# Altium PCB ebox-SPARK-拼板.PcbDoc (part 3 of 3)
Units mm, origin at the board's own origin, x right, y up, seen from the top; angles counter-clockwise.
Board outline 102 x 90 mm, 2 copper layers (Top Layer, Bottom Layer); 141 components, 68 nets, 621 pads, 146 vias.
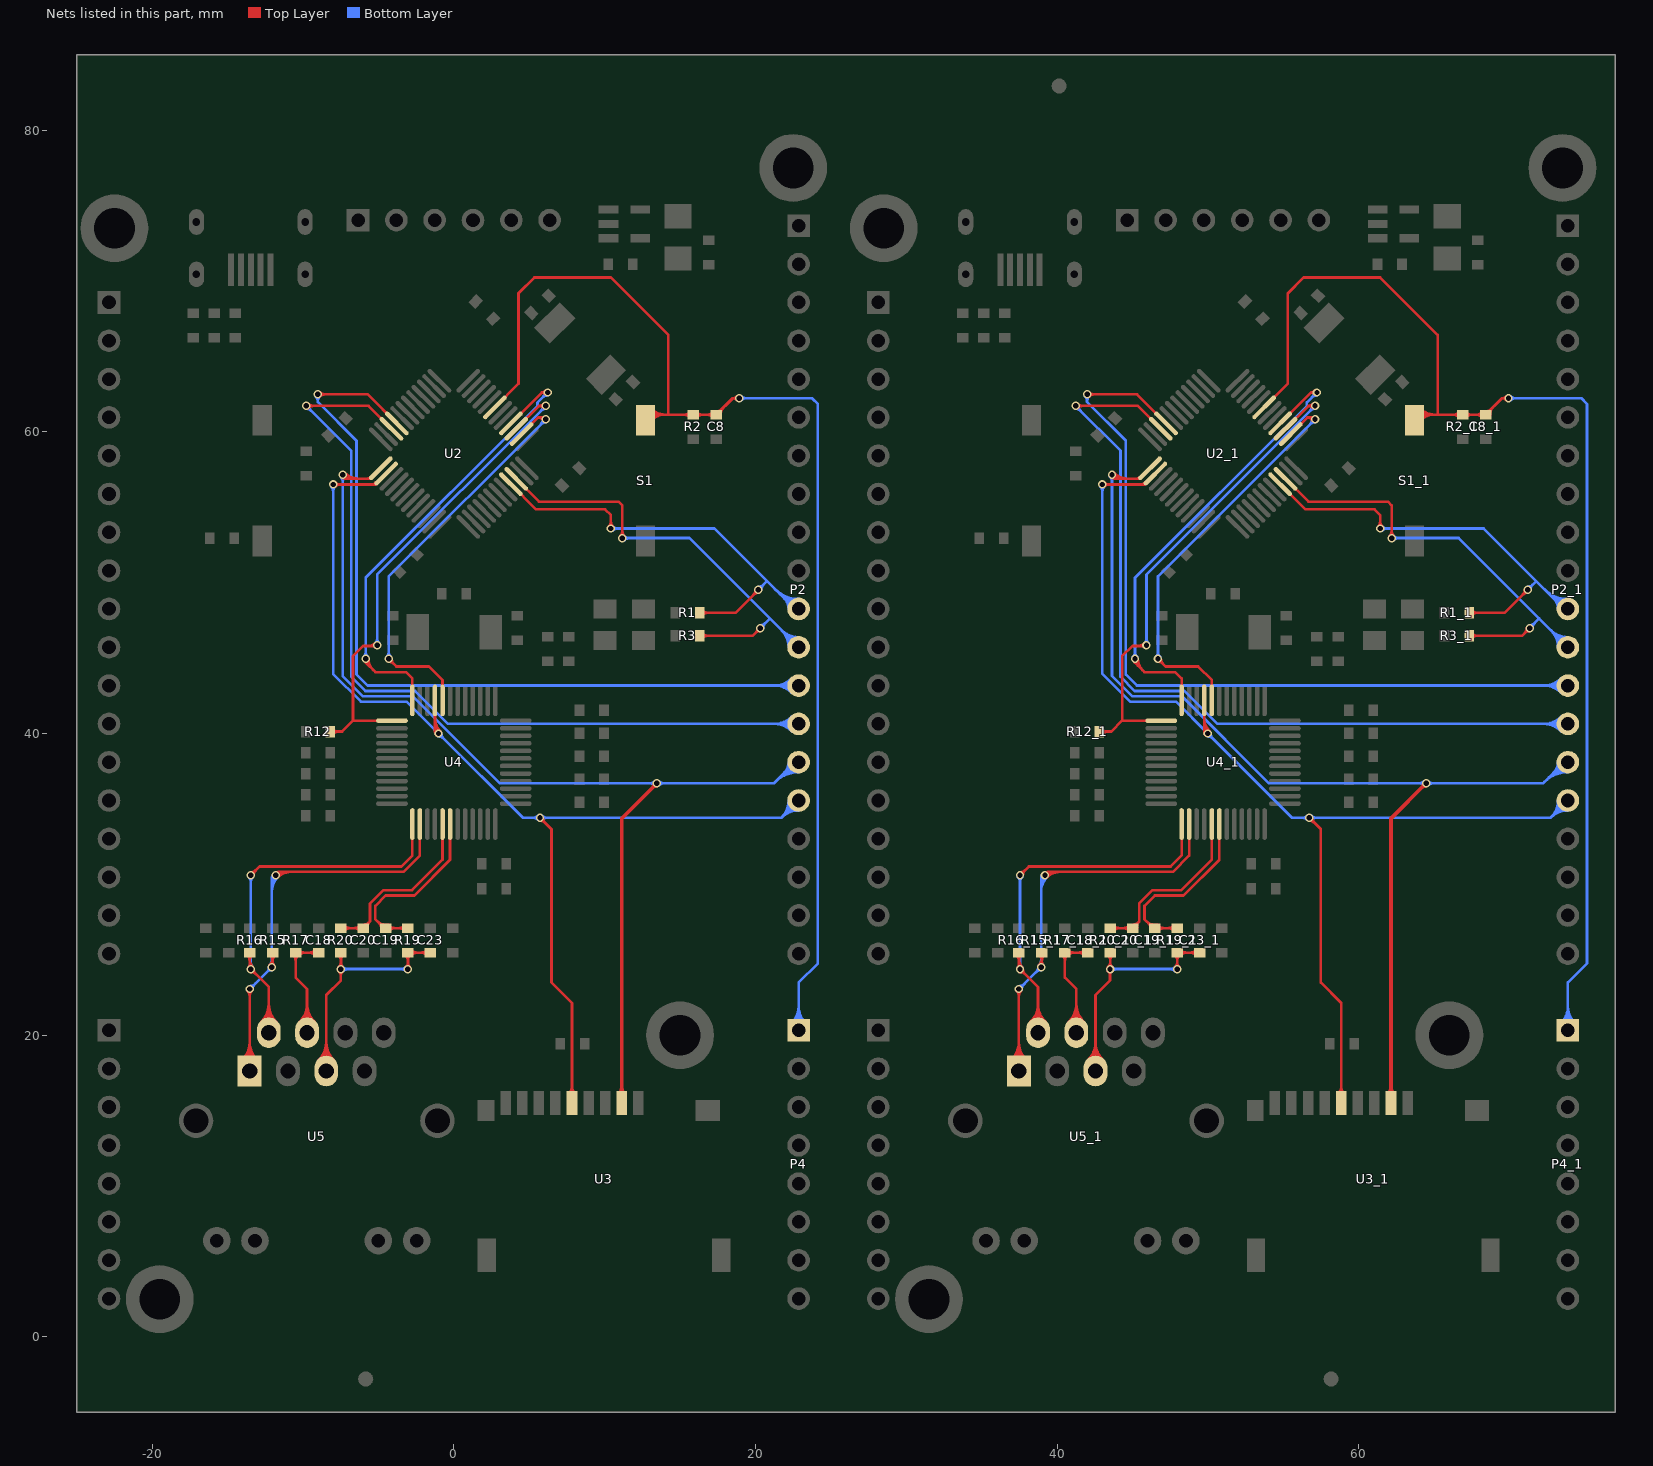
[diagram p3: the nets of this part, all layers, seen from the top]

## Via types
v1: diameter 0.559, hole 0.356, Top Layer to Bottom Layer, tented both sides, 140 vias
v2: diameter 1, hole 1, Top Layer to Bottom Layer, tented both sides, 4 vias
v3: diameter 1.27, hole 0.711, Top Layer to Bottom Layer, tented both sides, 2 vias

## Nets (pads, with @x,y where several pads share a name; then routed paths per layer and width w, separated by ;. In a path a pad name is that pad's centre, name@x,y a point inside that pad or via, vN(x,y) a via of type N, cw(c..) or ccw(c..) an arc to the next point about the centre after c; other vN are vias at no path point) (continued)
PB8: P2.11 P2_1.11 R1.1 R1_1.1 U2.45 U2_1.45 | length 76.4
  Top Layer w0.178: U2.45@3.783,56.532 5.451,54.864 10.033,54.864 10.414,54.483 v1(10.414,53.594) ; v1@10.279,53.729 ccw(c9.954,54.054) 10.414,54.054 ccw(c10.874,54.054) v1@10.549,53.729 ; R1.1@16.307,48.006 18.669,48.006 v1(20.193,49.53) ; R1.1@16.468,47.844 cw(c16.859,47.454) 16.859,48.006 cw(c16.859,48.558) R1.1@16.468,48.168 ; v1@20.002,49.53 cw(c19.543,49.53) 19.868,49.205 cw(c20.193,48.88) v1@20.193,49.34 ; U2_1.45@54.783,56.532 56.451,54.864 61.033,54.864 61.414,54.483 v1(61.414,53.594) ; v1@61.279,53.729 ccw(c60.954,54.054) 61.414,54.054 ccw(c61.874,54.054) v1@61.549,53.729 ; R1_1.1@67.307,48.006 69.669,48.006 v1(71.193,49.53) ; R1_1.1@67.468,47.844 cw(c67.859,47.454) 67.859,48.006 cw(c67.859,48.558) R1_1.1@67.468,48.168 ; v1@71.002,49.53 cw(c70.543,49.53) 70.868,49.205 cw(c71.193,48.88) v1@71.193,49.34
  Bottom Layer w0.178: v1(10.414,53.594) 17.272,53.594 22.606,48.26 P2.11@22.86,48.26 ; v1@10.549,53.459 cw(c10.874,53.134) 10.874,53.594 cw(c10.874,54.054) v1@10.549,53.729 ; v1(20.193,49.53) 20.735,50.072 ; v1@20.193,49.721 ccw(c20.193,50.18) 20.518,49.855 ccw(c20.843,49.53) v1@20.383,49.53 ; 21.298,49.568 ccw(c22.86,51.13) P2.11@22.86,48.921 ; 21.601,49.265 ccw(c22.86,50.523) P2.11@22.86,48.743 ; 21.905,48.961 ccw(c22.86,49.916) P2.11@22.86,48.565 ; 21.911,48.955 cw(c21.216,48.26) P2.11@22.199,48.26 ; 22.208,48.658 ccw(c22.86,49.309) P2.11@22.86,48.388 ; 22.215,48.651 cw(c21.823,48.26) P2.11@22.377,48.26 ; v1(61.414,53.594) 68.272,53.594 73.606,48.26 P2_1.11@73.86,48.26 ; v1@61.549,53.459 cw(c61.874,53.134) 61.874,53.594 cw(c61.874,54.054) v1@61.549,53.729 ; v1(71.193,49.53) 71.735,50.072 ; v1@71.193,49.721 ccw(c71.193,50.18) 71.518,49.855 ccw(c71.843,49.53) v1@71.383,49.53 ; 72.298,49.568 ccw(c73.86,51.13) P2_1.11@73.86,48.921 ; 72.601,49.265 ccw(c73.86,50.523) P2_1.11@73.86,48.743 ; 72.905,48.961 ccw(c73.86,49.916) P2_1.11@73.86,48.565 ; 72.911,48.955 cw(c72.216,48.26) P2_1.11@73.199,48.26 ; 73.208,48.658 ccw(c73.86,49.309) P2_1.11@73.86,48.388 ; 73.215,48.651 cw(c72.823,48.26) P2_1.11@73.377,48.26
PB9: P2.12 P2_1.12 R3.1 R3_1.1 U2.46 U2_1.46 | length 75.9
  Top Layer w0.178: U2.46@4.137,56.885 5.65,55.372 10.922,55.372 11.176,55.118 v1(11.176,52.959) ; v1@11.041,53.094 ccw(c10.716,53.419) 11.176,53.419 ccw(c11.636,53.419) v1@11.311,53.094 ; R3.1@16.307,46.482 19.812,46.482 v1(20.32,46.99) v1@20.193,46.99 ; R3.1@16.468,46.32 cw(c16.859,45.93) 16.859,46.482 cw(c16.859,47.034) R3.1@16.468,46.644 ; v1@20.13,46.99 cw(c19.67,46.99) 19.995,46.665 cw(c20.32,46.34) v1@20.32,46.799 ; U2_1.46@55.137,56.885 56.65,55.372 61.922,55.372 62.176,55.118 v1(62.176,52.959) ; v1@62.041,53.094 ccw(c61.716,53.419) 62.176,53.419 ccw(c62.636,53.419) v1@62.311,53.094 ; R3_1.1@67.307,46.482 70.812,46.482 v1(71.32,46.99) v1@71.193,46.99 ; R3_1.1@67.468,46.32 cw(c67.859,45.93) 67.859,46.482 cw(c67.859,47.034) R3_1.1@67.468,46.644 ; v1@71.129,46.99 cw(c70.67,46.99) 70.995,46.665 cw(c71.32,46.34) v1@71.32,46.799
  Bottom Layer w0.178: v1(11.176,52.959) 15.621,52.959 20.955,47.625 ; v1@11.311,52.824 cw(c11.636,52.499) 11.636,52.959 cw(c11.636,53.419) v1@11.311,53.094 ; v1(20.32,46.99) 20.955,47.625 ; v1@20.32,47.18 ccw(c20.32,47.64) 20.645,47.315 ccw(c20.97,46.99) v1@20.51,46.99 ; P2.12@22.199,45.72 ccw(c20.603,45.72) 21.731,46.849 ccw(c22.86,47.977) P2.12@22.86,46.381 ; P2.12@22.377,45.72 ccw(c21.21,45.72) 22.035,46.545 ccw(c22.86,47.37) P2.12@22.86,46.203 ; P2.12@22.86,45.72 20.955,47.625 ; v1(62.176,52.959) 66.621,52.959 71.955,47.625 ; v1@62.311,52.824 cw(c62.636,52.499) 62.636,52.959 cw(c62.636,53.419) v1@62.311,53.094 ; v1(71.32,46.99) 71.955,47.625 ; v1@71.32,47.18 ccw(c71.32,47.64) 71.645,47.315 ccw(c71.97,46.99) v1@71.51,46.99 ; P2_1.12@73.199,45.72 ccw(c71.603,45.72) 72.731,46.849 ccw(c73.86,47.977) P2_1.12@73.86,46.381 ; P2_1.12@73.377,45.72 ccw(c72.21,45.72) 73.035,46.545 ccw(c73.86,47.37) P2_1.12@73.86,46.203 ; P2_1.12@73.86,45.72 71.955,47.625
PB10: P2.13 P2_1.13 U2.21 U2_1.21 | length 122.1
  Top Layer w0.178: v1(-9.017,62.484) -5.705,62.484 U2.21@-3.783,60.562 ; v1@-8.882,62.349 cw(c-8.557,62.024) -8.557,62.484 cw(c-8.557,62.944) v1@-8.882,62.619 ; v1(41.983,62.484) 45.295,62.484 U2_1.21@47.217,60.562 ; v1@42.118,62.349 cw(c42.443,62.024) 42.443,62.484 cw(c42.443,62.944) v1@42.118,62.619
  Bottom Layer w0.178: v1@-9.152,62.349 cw(c-9.477,62.024) -9.017,62.024 cw(c-8.557,62.024) v1@-8.882,62.349 ; v1(-9.017,62.484) -9.017,61.976 -6.452,59.411 -6.452,43.917 -5.715,43.18 19.558,43.18 P2.13@22.86,43.18 ; P2.13@22.393,42.713 ccw(c21.264,41.584) 21.264,43.18 ccw(c21.264,44.776) P2.13@22.393,43.647 ; P2.13@22.518,42.838 ccw(c21.693,42.013) 21.693,43.18 ccw(c21.693,44.347) P2.13@22.518,43.522 ; v1@41.848,62.349 cw(c41.523,62.024) 41.983,62.024 cw(c42.443,62.024) v1@42.118,62.349 ; v1(41.983,62.484) 41.983,61.976 44.548,59.411 44.548,43.917 45.285,43.18 70.558,43.18 P2_1.13@73.86,43.18 ; P2_1.13@73.393,42.713 ccw(c72.264,41.584) 72.264,43.18 ccw(c72.264,44.776) P2_1.13@73.393,43.647 ; P2_1.13@73.518,42.838 ccw(c72.693,42.013) 72.693,43.18 ccw(c72.693,44.347) P2_1.13@73.518,43.522
PB11: P2.14 P2_1.14 U2.22 U2_1.22 | length 124.4
  Top Layer w0.178: v1(-9.779,61.722) -5.65,61.722 U2.22@-4.137,60.209 ; v1@-9.644,61.587 cw(c-9.319,61.262) -9.319,61.722 cw(c-9.319,62.182) v1@-9.644,61.857 ; v1(41.221,61.722) 45.35,61.722 U2_1.22@46.863,60.209 ; v1@41.356,61.587 cw(c41.681,61.262) 41.681,61.722 cw(c41.681,62.182) v1@41.356,61.857
  Bottom Layer w0.178: v1@-9.779,61.531 cw(c-9.779,61.072) -9.454,61.397 cw(c-9.129,61.722) v1@-9.589,61.722 ; v1(-9.779,61.722) -6.807,58.75 -6.807,43.769 -5.862,42.824 -2.56,42.824 -0.376,40.64 P2.14@22.86,40.64 ; P2.14@22.393,40.173 ccw(c21.264,39.044) 21.264,40.64 ccw(c21.264,42.236) P2.14@22.393,41.107 ; P2.14@22.518,40.298 ccw(c21.693,39.473) 21.693,40.64 ccw(c21.693,41.807) P2.14@22.518,40.982 ; v1@41.221,61.531 cw(c41.221,61.072) 41.546,61.397 cw(c41.871,61.722) v1@41.411,61.722 ; v1(41.221,61.722) 44.193,58.75 44.193,43.769 45.138,42.824 48.44,42.824 50.624,40.64 P2_1.14@73.86,40.64 ; P2_1.14@73.393,40.173 ccw(c72.264,39.044) 72.264,40.64 ccw(c72.264,42.236) P2_1.14@73.393,41.107 ; P2_1.14@73.518,40.298 ccw(c72.693,39.473) 72.693,40.64 ccw(c72.693,41.807) P2_1.14@73.518,40.982
PB12: P2.15 P2_1.15 U2.25 U2_1.25 U3.2 U3_1.2 | length 168.5
  Top Layer w0.178: v1@-7.483,57.033 ccw(c-7.151,57.365) -7.151,56.896 ; v1(-7.366,57.15) -7.112,56.896 -5.54,56.896 U2.25@-4.844,57.592 ; v1@-7.357,57.159 ccw(c-6.722,57.794) -6.722,56.896 ; v1@-7.231,57.285 ccw(c-6.293,58.223) -6.293,56.896 ; -5.772,56.896 ccw(c-5.772,57.248) U2.25@-5.523,56.999 ; v1@43.517,57.033 ccw(c43.849,57.365) 43.849,56.896 ; v1(43.634,57.15) 43.888,56.896 45.46,56.896 U2_1.25@46.156,57.592 ; v1@43.643,57.159 ccw(c44.278,57.794) 44.278,56.896 ; v1@43.769,57.285 ccw(c44.707,58.223) 44.707,56.896 ; 45.228,56.896 ccw(c45.228,57.248) U2_1.25@45.477,56.999
  Top Layer w0.254: U3.2@10.975,16.122 ccw(c10.594,16.503) 11.133,16.503 ccw(c11.671,16.503) U3.2@11.29,16.122 ; U3.2@11.133,15.515 11.133,34.374 v1(13.462,36.703) ; v1@13.31,36.703 cw(c12.942,36.703) 13.202,36.443 cw(c13.462,36.183) v1@13.462,36.551 ; U3_1.2@61.975,16.122 ccw(c61.594,16.503) 62.133,16.503 ccw(c62.671,16.503) U3_1.2@62.29,16.122 ; U3_1.2@62.133,15.515 62.133,34.374 v1(64.462,36.703) ; v1@64.31,36.703 cw(c63.942,36.703) 64.202,36.443 cw(c64.462,36.183) v1@64.462,36.551
  Bottom Layer w0.178: v1@-7.501,57.015 cw(c-7.826,56.69) -7.366,56.69 cw(c-6.906,56.69) v1@-7.231,57.015 ; v1(-7.366,57.15) -7.366,43.825 -6.01,42.469 -2.708,42.469 3.058,36.703 v1(13.462,36.703) 21.209,36.703 22.606,38.1 P2.15@22.86,38.1 ; v1@13.327,36.568 ccw(c13.002,36.243) 13.002,36.703 ccw(c13.002,37.163) v1@13.327,36.838 ; v1@13.597,36.568 cw(c13.922,36.243) 13.922,36.703 cw(c13.922,37.163) v1@13.597,36.838 ; 21.298,36.792 cw(c22.86,35.23) P2.15@22.86,37.439 ; 21.601,37.095 cw(c22.86,35.837) P2.15@22.86,37.617 ; 21.905,37.399 cw(c22.86,36.444) P2.15@22.86,37.795 ; 21.911,37.405 ccw(c21.216,38.1) P2.15@22.199,38.1 ; 22.208,37.702 cw(c22.86,37.051) P2.15@22.86,37.972 ; 22.215,37.709 ccw(c21.823,38.1) P2.15@22.377,38.1 ; v1@43.499,57.015 cw(c43.174,56.69) 43.634,56.69 cw(c44.094,56.69) v1@43.769,57.015 ; v1(43.634,57.15) 43.634,43.825 44.99,42.469 48.292,42.469 54.058,36.703 v1(64.462,36.703) 72.209,36.703 73.606,38.1 P2_1.15@73.86,38.1 ; v1@64.327,36.568 ccw(c64.002,36.243) 64.002,36.703 ccw(c64.002,37.163) v1@64.327,36.838 ; v1@64.597,36.568 cw(c64.922,36.243) 64.922,36.703 cw(c64.922,37.163) v1@64.597,36.838 ; 72.298,36.792 cw(c73.86,35.23) P2_1.15@73.86,37.439 ; 72.601,37.095 cw(c73.86,35.837) P2_1.15@73.86,37.617 ; 72.905,37.399 cw(c73.86,36.444) P2_1.15@73.86,37.795 ; 72.911,37.405 ccw(c72.216,38.1) P2_1.15@73.199,38.1 ; 73.208,37.702 cw(c73.86,37.051) P2_1.15@73.86,37.972 ; 73.215,37.709 ccw(c72.823,38.1) P2_1.15@73.377,38.1
PB13: P2.16 P2_1.16 U2.26 U2_1.26 U3.5 U3_1.5 U4.33 U4_1.33 | length 172.8
  Top Layer w0.178: v1(-8.001,56.515) -5.214,56.515 U2.26@-4.49,57.239 ; v1@-7.866,56.38 cw(c-7.541,56.055) -7.541,56.515 cw(c-7.541,56.975) v1@-7.866,56.65 ; -5.485,56.515 ccw(c-5.485,56.961) U2.26@-5.17,56.646 ; -1.25,40.171 ccw(c-0.85,40.171) v1@-1.133,39.888 ; -1.25,40.601 ccw(c-0.42,40.601) v1@-1.007,40.014 ; -1.25,41.03 ccw(c0.009,41.03) v1@-0.881,40.14 ; U4.33@-1.25,42.2 -1.25,40.239 v1(-1.016,40.005) ; v1@5.715,34.227 cw(c5.715,33.767) 6.04,34.092 cw(c6.365,34.417) v1@5.905,34.417 ; v1(5.715,34.417) 6.477,33.655 6.477,23.495 7.833,22.139 U3.5@7.833,15.515 ; U3.5@7.648,16.149 ccw(c7.202,16.595) 7.833,16.595 ccw(c8.463,16.595) U3.5@8.017,16.149 ; v1(42.999,56.515) 45.786,56.515 U2_1.26@46.51,57.239 ; v1@43.134,56.38 cw(c43.459,56.055) 43.459,56.515 cw(c43.459,56.975) v1@43.134,56.65 ; 45.515,56.515 ccw(c45.515,56.961) U2_1.26@45.83,56.646 ; 49.75,40.171 ccw(c50.15,40.171) v1@49.867,39.888 ; 49.75,40.601 ccw(c50.58,40.601) v1@49.993,40.014 ; 49.75,41.03 ccw(c51.009,41.03) v1@50.119,40.14 ; U4_1.33@49.75,42.2 49.75,40.239 v1(49.984,40.005) ; v1@56.715,34.227 cw(c56.715,33.767) 57.04,34.092 cw(c57.365,34.417) v1@56.905,34.417 ; v1(56.715,34.417) 57.477,33.655 57.477,23.495 58.833,22.139 U3_1.5@58.833,15.515 ; U3_1.5@58.648,16.149 ccw(c58.202,16.595) 58.833,16.595 ccw(c59.463,16.595) U3_1.5@59.017,16.149
  Bottom Layer w0.178: v1@-8.136,56.38 cw(c-8.461,56.055) -8.001,56.055 cw(c-7.541,56.055) v1@-7.866,56.38 ; v1(-8.001,56.515) -8.001,43.957 -6.157,42.113 -3.124,42.113 v1(-1.016,40.005) 4.572,34.417 21.717,34.417 P2.16@22.86,35.56 ; v1@-1.206,40.005 ccw(c-1.666,40.005) -1.341,40.33 ccw(c-1.016,40.655) v1@-1.016,40.195 ; v1@-1.016,39.814 cw(c-1.016,39.355) -0.691,39.68 cw(c-0.366,40.005) v1@-0.826,40.005 ; v1@5.58,34.282 ccw(c5.255,33.957) 5.255,34.417 ccw(c5.255,34.877) v1@5.58,34.552 ; v1@5.85,34.282 cw(c6.175,33.957) 6.175,34.417 cw(c6.175,34.877) v1@5.85,34.552 ; P2.16@22.199,35.56 cw(c20.603,35.56) 21.731,34.431 cw(c22.86,33.303) P2.16@22.86,34.899 ; P2.16@22.377,35.56 cw(c21.21,35.56) 22.035,34.735 cw(c22.86,33.91) P2.16@22.86,35.077 ; v1@42.864,56.38 cw(c42.539,56.055) 42.999,56.055 cw(c43.459,56.055) v1@43.134,56.38 ; v1(42.999,56.515) 42.999,43.957 44.843,42.113 47.876,42.113 v1(49.984,40.005) 55.572,34.417 72.717,34.417 P2_1.16@73.86,35.56 ; v1@49.793,40.005 ccw(c49.334,40.005) 49.659,40.33 ccw(c49.984,40.655) v1@49.984,40.195 ; v1@49.984,39.814 cw(c49.984,39.355) 50.309,39.68 cw(c50.634,40.005) v1@50.174,40.005 ; v1@56.58,34.282 ccw(c56.255,33.957) 56.255,34.417 ccw(c56.255,34.877) v1@56.58,34.552 ; v1@56.85,34.282 cw(c57.175,33.957) 57.175,34.417 cw(c57.175,34.877) v1@56.85,34.552 ; P2_1.16@73.199,35.56 cw(c71.603,35.56) 72.731,34.431 cw(c73.86,33.303) P2_1.16@73.86,34.899 ; P2_1.16@73.377,35.56 cw(c72.21,35.56) 73.035,34.735 cw(c73.86,33.91) P2_1.16@73.86,35.077
PC13: U2.2 U2_1.2 U4.32 U4_1.32 | length 60.9
  Top Layer w0.178: v1@-4.318,44.767 cw(c-4.318,44.308) -3.993,44.633 cw(c-3.668,44.958) v1@-4.128,44.958 ; v1(-4.318,44.958) -3.81,44.45 -1.651,44.45 -0.75,43.549 U4.32@-0.75,42.2 ; U2.2@4.49,59.855 5.595,60.96 ; v1@5.924,60.752 ccw(c5.595,60.596) 5.595,60.96 ; v1(6.096,60.833) 6.096,60.96 5.595,60.96 ; v1@46.682,44.767 cw(c46.682,44.308) 47.007,44.633 cw(c47.332,44.958) v1@46.872,44.958 ; v1(46.682,44.958) 47.19,44.45 49.349,44.45 50.25,43.549 U4_1.32@50.25,42.2 ; U2_1.2@55.49,59.855 56.595,60.96 ; v1@56.924,60.752 ccw(c56.595,60.596) 56.595,60.96 ; v1(57.096,60.833) 57.096,60.96 56.595,60.96
  Bottom Layer w0.178: v1@-4.453,45.093 ccw(c-4.778,45.418) -4.318,45.418 ccw(c-3.858,45.418) v1@-4.183,45.093 ; v1(-4.318,44.958) -4.318,50.419 v1(6.096,60.833) ; v1@5.905,60.833 cw(c5.446,60.833) 5.771,60.508 cw(c6.096,60.183) v1@6.096,60.642 ; v1@46.547,45.093 ccw(c46.222,45.418) 46.682,45.418 ccw(c47.142,45.418) v1@46.817,45.093 ; v1(46.682,44.958) 46.682,50.419 v1(57.096,60.833) ; v1@56.905,60.833 cw(c56.446,60.833) 56.771,60.508 cw(c57.096,60.183) v1@57.096,60.642
PC14: R12.1 R12_1.1 U2.3 U2_1.3 U4.37 U4_1.37 | length 74.8
  Top Layer w0.178: R12.1@-8.204,40.132 -7.405,40.132 -6.687,40.85 ; R12.1@-8.043,39.97 cw(c-7.652,39.58) -7.652,40.132 cw(c-7.652,40.684) R12.1@-8.043,40.294 ; -5.643,45.805 ccw(c-5.643,46.41) v1@-5.215,45.982 ; -5.437,45.805 cw(c-5.437,45.49) v1@-5.215,45.712 ; v1(-5.08,45.847) -5.122,45.805 -6.011,45.805 -6.687,45.129 -6.687,40.85 ; U4.37@-4.1,40.85 -6.687,40.85 ; U2.3@4.137,60.209 5.65,61.722 ; v1@5.958,61.59 ccw(c5.65,61.295) 5.65,61.722 ; v1@5.958,61.854 cw(c5.65,62.149) 5.65,61.722 ; v1(6.096,61.722) 5.65,61.722 ; R12_1.1@42.796,40.132 43.595,40.132 44.313,40.85 ; R12_1.1@42.957,39.97 cw(c43.348,39.58) 43.348,40.132 cw(c43.348,40.684) R12_1.1@42.957,40.294 ; 45.357,45.805 ccw(c45.357,46.41) v1@45.785,45.982 ; 45.563,45.805 cw(c45.563,45.49) v1@45.785,45.712 ; v1(45.92,45.847) 45.878,45.805 44.989,45.805 44.313,45.129 44.313,40.85 ; U4_1.37@46.9,40.85 44.313,40.85 ; U2_1.3@55.137,60.209 56.65,61.722 ; v1@56.958,61.59 ccw(c56.65,61.295) 56.65,61.722 ; v1@56.958,61.854 cw(c56.65,62.149) 56.65,61.722 ; v1(57.096,61.722) 56.65,61.722
  Bottom Layer w0.178: v1@-5.215,45.982 ccw(c-5.54,46.307) -5.08,46.307 ccw(c-4.62,46.307) v1@-4.945,45.982 ; v1(-5.08,45.847) -5.08,50.546 v1(6.096,61.722) ; v1@5.905,61.722 cw(c5.446,61.722) 5.771,61.397 cw(c6.096,61.072) v1@6.096,61.531 ; v1@45.785,45.982 ccw(c45.46,46.307) 45.92,46.307 ccw(c46.38,46.307) v1@46.055,45.982 ; v1(45.92,45.847) 45.92,50.546 v1(57.096,61.722) ; v1@56.905,61.722 cw(c56.446,61.722) 56.771,61.397 cw(c57.096,61.072) v1@57.096,61.531
PC15: U2.4 U2_1.4 U4.36 U4_1.36 | length 69
  Top Layer w0.178: v1(-5.842,44.958) -5.842,44.704 -5.207,44.069 -3.175,44.069 -2.75,43.644 U4.36@-2.75,42.2 ; v1@-5.829,44.958 ccw(c-5.185,44.958) -5.641,44.503 ; v1@-5.652,44.958 ccw(c-4.578,44.958) -5.337,44.199 ; U2.4@3.783,60.562 5.832,62.611 ; v1@6.073,62.494 ccw(c5.832,62.305) 5.832,62.611 ; v1@6.073,62.728 cw(c5.832,62.917) 5.832,62.611 ; v1(6.223,62.611) 5.832,62.611 ; v1(45.158,44.958) 45.158,44.704 45.793,44.069 47.825,44.069 48.25,43.644 U4_1.36@48.25,42.2 ; v1@45.171,44.958 ccw(c45.815,44.958) 45.359,44.503 ; v1@45.348,44.958 ccw(c46.422,44.958) 45.663,44.199 ; U2_1.4@54.783,60.562 56.832,62.611 ; v1@57.073,62.494 ccw(c56.832,62.305) 56.832,62.611 ; v1@57.073,62.728 cw(c56.832,62.917) 56.832,62.611 ; v1(57.223,62.611) 56.832,62.611
  Bottom Layer w0.178: v1@-5.977,45.093 ccw(c-6.302,45.418) -5.842,45.418 ccw(c-5.382,45.418) v1@-5.707,45.093 ; v1(-5.842,44.958) -5.842,50.328 5.55,61.72 5.55,61.948 6.213,62.611 v1(6.223,62.611) ; 5.88,62.279 cw(c6.223,61.936) v1@6.223,62.42 ; 5.905,62.303 ccw(c5.597,62.611) v1@6.032,62.611 ; v1@45.023,45.093 ccw(c44.698,45.418) 45.158,45.418 ccw(c45.618,45.418) v1@45.293,45.093 ; v1(45.158,44.958) 45.158,50.328 56.55,61.72 56.55,61.948 57.213,62.611 v1(57.223,62.611) ; 56.88,62.279 cw(c57.223,61.936) v1@57.223,62.42 ; 56.905,62.303 ccw(c56.597,62.611) v1@57.032,62.611
RCT: C23.1 C23_1.1 R19.2 R19_1.2 R20.2 R20_1.2 U5.5 U5_1.5 | length 56.6
  Top Layer w0.178: U5.5@-8.953,18.35 ccw(c-10.145,19.543) -8.459,19.543 ccw(c-6.772,19.543) U5.5@-7.965,18.35 ; U5.5@-8.827,18.224 ccw(c-9.716,19.113) -8.459,19.113 ccw(c-7.202,19.113) U5.5@-8.09,18.224 ; U5.5@-8.701,18.099 ccw(c-9.286,18.684) -8.459,18.684 ccw(c-7.631,18.684) U5.5@-8.216,18.099 ; U5.5@-8.459,17.628 -8.459,22.656 -7.493,23.622 v1(-7.493,24.384) -7.485,24.392 R20.2@-7.485,25.476 ; R20.2@-7.646,25.315 cw(c-8.036,24.924) -7.485,24.924 cw(c-6.933,24.924) R20.2@-7.323,25.315 ; v1@-7.628,24.249 cw(c-7.953,23.924) -7.493,23.924 cw(c-7.033,23.924) v1@-7.358,24.249 ; v1@-7.628,24.519 ccw(c-7.973,24.864) -7.485,24.864 ; -7.485,24.823 ccw(c-7.054,24.823) v1@-7.358,24.519 ; R19.2@-3.201,25.315 cw(c-3.591,24.924) -3.04,24.924 cw(c-2.488,24.924) R19.2@-2.878,25.315 ; v1@-3.183,24.519 ccw(c-3.528,24.864) -3.04,24.864 ; v1(-3.048,24.384) -3.04,24.392 R19.2@-3.04,25.476 C23.1@-1.558,25.476 ; -3.04,24.823 ccw(c-2.609,24.823) v1@-2.913,24.519 ; R19.2@-2.814,25.315 cw(c-2.424,24.924) -2.424,25.476 cw(c-2.424,26.028) R19.2@-2.814,25.638 ; C23.1@-1.783,25.315 ccw(c-2.173,24.924) -2.173,25.476 ccw(c-2.173,26.028) C23.1@-1.783,25.638 ; U5_1.5@42.047,18.35 ccw(c40.855,19.543) 42.541,19.543 ccw(c44.228,19.543) U5_1.5@43.035,18.35 ; U5_1.5@42.173,18.224 ccw(c41.284,19.113) 42.541,19.113 ccw(c43.798,19.113) U5_1.5@42.91,18.224 ; U5_1.5@42.299,18.099 ccw(c41.714,18.684) 42.541,18.684 ccw(c43.369,18.684) U5_1.5@42.784,18.099 ; U5_1.5@42.541,17.628 42.541,22.656 43.507,23.622 v1(43.507,24.384) 43.515,24.392 R20_1.2@43.515,25.476 ; R20_1.2@43.354,25.315 cw(c42.964,24.924) 43.515,24.924 cw(c44.067,24.924) R20_1.2@43.677,25.315 ; v1@43.372,24.249 cw(c43.047,23.924) 43.507,23.924 cw(c43.967,23.924) v1@43.642,24.249 ; v1@43.372,24.519 ccw(c43.027,24.864) 43.515,24.864 ; 43.515,24.823 ccw(c43.946,24.823) v1@43.642,24.519 ; R19_1.2@47.799,25.315 cw(c47.409,24.924) 47.96,24.924 cw(c48.512,24.924) R19_1.2@48.122,25.315 ; v1@47.817,24.519 ccw(c47.472,24.864) 47.96,24.864 ; v1(47.952,24.384) 47.96,24.392 R19_1.2@47.96,25.476 C23_1.1@49.442,25.476 ; 47.96,24.823 ccw(c48.391,24.823) v1@48.087,24.519 ; R19_1.2@48.186,25.315 cw(c48.576,24.924) 48.576,25.476 cw(c48.576,26.028) R19_1.2@48.186,25.638 ; C23_1.1@49.217,25.315 ccw(c48.827,24.924) 48.827,25.476 ccw(c48.827,26.028) C23_1.1@49.217,25.638
  Bottom Layer w0.178: v1(-7.493,24.384) v1(-3.048,24.384) ; v1@-7.358,24.249 cw(c-7.033,23.924) -7.033,24.384 cw(c-7.033,24.844) v1@-7.358,24.519 ; v1@-3.183,24.249 ccw(c-3.508,23.924) -3.508,24.384 ccw(c-3.508,24.844) v1@-3.183,24.519 ; v1(43.507,24.384) v1(47.952,24.384) ; v1@43.642,24.249 cw(c43.967,23.924) 43.967,24.384 cw(c43.967,24.844) v1@43.642,24.519 ; v1@47.817,24.249 ccw(c47.492,23.924) 47.492,24.384 ccw(c47.492,24.844) v1@47.817,24.519
RST: C8.1 C8_1.1 P4.1 P4_1.1 R2.2 R2_1.2 S1.2 S1_1.2 U2.7 U2_1.7 | length 184.7
  Top Layer w0.178: U2.7@2.722,61.623 4.293,63.193 4.293,69.19 5.334,70.231 8.001,70.231 10.414,70.231 14.224,66.421 14.224,61.138 ; S1.2@12.7,60.769 13.069,61.138 14.224,61.138 ; S1.2@12.96,60.89 cw(c13.56,60.29) 13.56,61.138 ; S1.2@12.96,61.41 ccw(c13.619,62.069) 13.619,61.138 ; S1.2@13.086,60.764 cw(c13.989,59.861) 13.989,61.138 ; S1.2@13.086,61.536 ccw(c14.048,62.498) 14.048,61.138 ; R2.2@15.65,60.976 ccw(c15.26,60.586) 15.26,61.138 ccw(c15.26,61.69) R2.2@15.65,61.299 ; R2.2@16.1,60.976 cw(c16.49,60.586) 16.49,61.138 cw(c16.49,61.69) R2.2@16.1,61.299 ; C8.1@17.174,60.976 ccw(c16.784,60.586) 16.784,61.138 ccw(c16.784,61.69) C8.1@17.174,61.299 ; C8.1@17.462,61.366 ccw(c17.462,61.765) 17.744,61.483 ; C8.1@17.691,61.138 cw(c18.396,61.138) 17.898,61.636 ; v1@18.782,62.102 ccw(c18.491,61.836) 18.491,62.23 ; v1@18.782,62.358 cw(c18.491,62.624) 18.491,62.23 ; v1(18.923,62.23) 18.491,62.23 ; U2_1.7@53.722,61.623 55.293,63.193 55.293,69.19 56.334,70.231 59.001,70.231 61.414,70.231 65.224,66.421 65.224,61.138 ; S1_1.2@63.7,60.769 64.069,61.138 65.224,61.138 ; S1_1.2@63.96,60.89 cw(c64.56,60.29) 64.56,61.138 ; S1_1.2@63.96,61.41 ccw(c64.619,62.069) 64.619,61.138 ; S1_1.2@64.086,60.764 cw(c64.989,59.861) 64.989,61.138 ; S1_1.2@64.086,61.536 ccw(c65.048,62.498) 65.048,61.138 ; R2_1.2@66.65,60.976 ccw(c66.26,60.586) 66.26,61.138 ccw(c66.26,61.69) R2_1.2@66.65,61.299 ; R2_1.2@67.1,60.976 cw(c67.49,60.586) 67.49,61.138 cw(c67.49,61.69) R2_1.2@67.1,61.299 ; C8_1.1@68.174,60.976 ccw(c67.784,60.586) 67.784,61.138 ccw(c67.784,61.69) C8_1.1@68.174,61.299 ; C8_1.1@68.462,61.366 ccw(c68.462,61.765) 68.744,61.483 ; C8_1.1@68.691,61.138 cw(c69.396,61.138) 68.898,61.636 ; v1@69.782,62.102 ccw(c69.491,61.836) 69.491,62.23 ; v1@69.782,62.358 cw(c69.491,62.624) 69.491,62.23 ; v1(69.923,62.23) 69.491,62.23 ; 14.224,61.138 R2.2@15.875,61.138 C8.1@17.399,61.138 18.491,62.23 ; 65.224,61.138 R2_1.2@66.875,61.138 C8_1.1@68.399,61.138 69.491,62.23
  Bottom Layer w0.178: v1(18.923,62.23) 23.749,62.23 24.13,61.849 24.13,24.765 22.86,23.495 P4.1@22.86,20.32 ; v1@19.058,62.095 cw(c19.383,61.77) 19.383,62.23 cw(c19.383,62.69) v1@19.058,62.365 ; P4.1@22.393,20.787 ccw(c21.264,21.916) 22.86,21.916 ccw(c24.456,21.916) P4.1@23.327,20.787 ; P4.1@22.518,20.662 ccw(c21.693,21.487) 22.86,21.487 ccw(c24.027,21.487) P4.1@23.202,20.662 ; v1(69.923,62.23) 74.749,62.23 75.13,61.849 75.13,24.765 73.86,23.495 P4_1.1@73.86,20.32 ; v1@70.058,62.095 cw(c70.383,61.77) 70.383,62.23 cw(c70.383,62.69) v1@70.058,62.365 ; P4_1.1@73.393,20.787 ccw(c72.264,21.916) 73.86,21.916 ccw(c75.456,21.916) P4_1.1@74.327,20.787 ; P4_1.1@73.518,20.662 ccw(c72.693,21.487) 73.86,21.487 ccw(c75.027,21.487) P4_1.1@74.202,20.662
RXN: C20.2 C20_1.2 R20.1 R20_1.1 U4.5 U4_1.5 | length 28.4
  Top Layer w0.178: R20.1@-7.485,27.102 C20.2@-6.003,27.102 -5.563,27.542 ; R20.1@-7.259,26.94 cw(c-6.869,26.55) -6.869,27.102 cw(c-6.869,27.654) R20.1@-7.259,27.263 ; C20.2@-6.228,26.94 ccw(c-6.618,26.55) -6.618,27.102 ccw(c-6.618,27.654) C20.2@-6.228,27.263 ; C20.2@-5.939,27.33 ccw(c-5.939,27.729) -5.658,27.447 ; C20.2@-5.712,27.124 cw(c-5.196,27.176) -5.563,27.542 ; U4.5@-0.75,34 -0.75,31.635 -2.769,29.616 -4.674,29.616 -5.563,28.727 -5.563,27.542 ; R20_1.1@43.515,27.102 C20_1.2@44.997,27.102 45.437,27.542 ; R20_1.1@43.741,26.94 cw(c44.131,26.55) 44.131,27.102 cw(c44.131,27.654) R20_1.1@43.741,27.263 ; C20_1.2@44.772,26.94 ccw(c44.382,26.55) 44.382,27.102 ccw(c44.382,27.654) C20_1.2@44.772,27.263 ; C20_1.2@45.061,27.33 ccw(c45.061,27.729) 45.342,27.447 ; C20_1.2@45.288,27.124 cw(c45.804,27.176) 45.437,27.542 ; U4_1.5@50.25,34 50.25,31.635 48.231,29.616 46.326,29.616 45.437,28.727 45.437,27.542
RXP: C19.2 C19_1.2 R19.1 R19_1.1 U4.6 U4_1.6 | length 29.2
  Top Layer w0.178: -5.04,27.519 ccw(c-4.585,27.974) C19.2@-4.585,27.33 ; -4.948,27.427 cw(c-5.273,27.102) C19.2@-4.813,27.102 ; C19.2@-4.521,27.102 R19.1@-3.04,27.102 ; C19.2@-4.318,27.305 -4.826,27.305 -5.207,27.686 -5.207,28.58 -4.526,29.261 -2.621,29.261 -0.25,31.632 U4.6@-0.25,34 ; C19.2@-4.296,26.94 cw(c-3.906,26.55) -3.906,27.102 cw(c-3.906,27.654) C19.2@-4.296,27.263 ; R19.1@-3.265,26.94 ccw(c-3.655,26.55) -3.655,27.102 ccw(c-3.655,27.654) R19.1@-3.265,27.263 ; 45.96,27.519 ccw(c46.415,27.974) C19_1.2@46.415,27.33 ; 46.052,27.427 cw(c45.727,27.102) C19_1.2@46.187,27.102 ; C19_1.2@46.479,27.102 R19_1.1@47.96,27.102 ; C19_1.2@46.682,27.305 46.174,27.305 45.793,27.686 45.793,28.58 46.474,29.261 48.379,29.261 50.75,31.632 U4_1.6@50.75,34 ; C19_1.2@46.704,26.94 cw(c47.094,26.55) 47.094,27.102 cw(c47.094,27.654) C19_1.2@46.704,27.263 ; R19_1.1@47.735,26.94 ccw(c47.345,26.55) 47.345,27.102 ccw(c47.345,27.654) R19_1.1@47.735,27.263
TCT: C18.2 C18_1.2 R17.1 R17_1.1 U5.4 U5_1.4 | length 31.8
  Top Layer w0.178: R17.1@-10.652,25.315 cw(c-11.042,24.924) -10.49,24.924 cw(c-9.938,24.924) R17.1@-10.329,25.315 ; R17.1@-10.265,25.315 cw(c-9.875,24.924) -9.875,25.476 cw(c-9.875,26.028) R17.1@-10.265,25.638 ; U5.4@-10.223,20.89 ccw(c-11.415,22.083) -9.729,22.083 ccw(c-8.042,22.083) U5.4@-9.235,20.89 ; U5.4@-10.097,20.764 ccw(c-10.986,21.653) -9.729,21.653 ccw(c-8.472,21.653) U5.4@-9.36,20.764 ; U5.4@-9.971,20.639 ccw(c-10.556,21.224) -9.729,21.224 ccw(c-8.901,21.224) U5.4@-9.486,20.639 ; U5.4@-9.729,20.168 -9.729,23.064 -10.49,23.825 R17.1@-10.49,25.476 C18.2@-8.966,25.476 ; C18.2@-9.191,25.315 ccw(c-9.582,24.924) -9.582,25.476 ccw(c-9.582,26.028) C18.2@-9.191,25.638 ; R17_1.1@40.348,25.315 cw(c39.958,24.924) 40.51,24.924 cw(c41.062,24.924) R17_1.1@40.671,25.315 ; R17_1.1@40.735,25.315 cw(c41.125,24.924) 41.125,25.476 cw(c41.125,26.028) R17_1.1@40.735,25.638 ; U5_1.4@40.777,20.89 ccw(c39.585,22.083) 41.271,22.083 ccw(c42.958,22.083) U5_1.4@41.765,20.89 ; U5_1.4@40.903,20.764 ccw(c40.014,21.653) 41.271,21.653 ccw(c42.528,21.653) U5_1.4@41.64,20.764 ; U5_1.4@41.029,20.639 ccw(c40.444,21.224) 41.271,21.224 ccw(c42.099,21.224) U5_1.4@41.514,20.639 ; U5_1.4@41.271,20.168 41.271,23.064 40.51,23.825 R17_1.1@40.51,25.476 C18_1.2@42.034,25.476 ; C18_1.2@41.809,25.315 ccw(c41.418,24.924) 41.418,25.476 ccw(c41.418,26.028) C18_1.2@41.809,25.638
  Bottom Layer w0.178: U5.4@-9.906,20.345 U5.4@-9.729,20.168 ; U5_1.4@41.094,20.345 U5_1.4@41.271,20.168
TXN: R16.1 R16_1.1 U4.1 U4_1.1 U5.2 U5_1.2 | length 71.4
  Top Layer w0.178: R16.1@-13.7,25.315 cw(c-14.09,24.924) -13.538,24.924 cw(c-12.986,24.924) R16.1@-13.377,25.315 ; v1@-13.597,24.514 ccw(c-13.738,24.655) -13.538,24.655 ; v1@-13.538,24.455 R16.1@-13.538,25.476 ; -13.538,25.023 ccw(c-12.818,25.023) v1@-13.327,24.514 ; v1@-13.462,24.188 cw(c-13.462,23.728) -13.137,24.054 cw(c-12.812,24.379) v1@-13.272,24.379 ; v1(-13.462,24.379) -12.269,23.185 U5.2@-12.269,20.168 ; v1(-13.462,30.607) -12.878,31.191 -3.48,31.191 -2.75,31.921 U4.1@-2.75,34 ; v1@-13.462,30.797 ccw(c-13.462,31.257) -13.137,30.932 ccw(c-12.812,30.607) v1@-13.272,30.607 ; U5.2@-12.763,20.89 ccw(c-13.955,22.083) -12.269,22.083 ccw(c-10.582,22.083) U5.2@-11.775,20.89 ; U5.2@-12.637,20.764 ccw(c-13.526,21.653) -12.269,21.653 ccw(c-11.012,21.653) U5.2@-11.9,20.764 ; U5.2@-12.511,20.639 ccw(c-13.096,21.224) -12.269,21.224 ccw(c-11.441,21.224) U5.2@-12.026,20.639 ; R16_1.1@37.3,25.315 cw(c36.91,24.924) 37.462,24.924 cw(c38.014,24.924) R16_1.1@37.623,25.315 ; v1@37.403,24.514 ccw(c37.262,24.655) 37.462,24.655 ; v1@37.462,24.455 R16_1.1@37.462,25.476 ; 37.462,25.023 ccw(c38.182,25.023) v1@37.673,24.514 ; v1@37.538,24.188 cw(c37.538,23.728) 37.863,24.054 cw(c38.188,24.379) v1@37.728,24.379 ; v1(37.538,24.379) 38.731,23.185 U5_1.2@38.731,20.168 ; v1(37.538,30.607) 38.122,31.191 47.52,31.191 48.25,31.921 U4_1.1@48.25,34 ; v1@37.538,30.797 ccw(c37.538,31.257) 37.863,30.932 ccw(c38.188,30.607) v1@37.728,30.607 ; U5_1.2@38.237,20.89 ccw(c37.045,22.083) 38.731,22.083 ccw(c40.418,22.083) U5_1.2@39.225,20.89 ; U5_1.2@38.363,20.764 ccw(c37.474,21.653) 38.731,21.653 ccw(c39.988,21.653) U5_1.2@39.1,20.764 ; U5_1.2@38.489,20.639 ccw(c37.904,21.224) 38.731,21.224 ccw(c39.559,21.224) U5_1.2@38.974,20.639
  Bottom Layer w0.178: v1@-13.597,24.514 ccw(c-13.922,24.839) -13.462,24.839 ccw(c-13.002,24.839) v1@-13.327,24.514 ; v1@-13.597,30.472 cw(c-13.922,30.147) -13.462,30.147 cw(c-13.002,30.147) v1@-13.327,30.472 ; v1(-13.462,24.379) v1(-13.462,30.607) ; v1@37.403,24.514 ccw(c37.078,24.839) 37.538,24.839 ccw(c37.998,24.839) v1@37.673,24.514 ; v1@37.403,30.472 cw(c37.078,30.147) 37.538,30.147 cw(c37.998,30.147) v1@37.673,30.472 ; v1(37.538,24.379) v1(37.538,30.607)
TXP: R15.1 R15_1.1 U4.2 U4_1.2 U5.1 U5_1.1 | length 82.1
  Top Layer w0.178: U5.1@-14.033,18.35 ccw(c-15.225,19.543) -13.539,19.543 ccw(c-11.852,19.543) U5.1@-13.045,18.35 ; U5.1@-13.907,18.224 ccw(c-14.796,19.113) -13.539,19.113 ccw(c-12.282,19.113) U5.1@-13.17,18.224 ; U5.1@-13.781,18.099 ccw(c-14.366,18.684) -13.539,18.684 ccw(c-12.711,18.684) U5.1@-13.296,18.099 ; v1@-13.673,22.929 cw(c-13.999,22.604) -13.539,22.604 cw(c-13.079,22.604) v1@-13.404,22.929 ; U5.1@-13.539,17.628 v1(-13.539,23.064) ; v1@-12.2,24.646 ccw(c-12.648,25.094) -12.014,25.094 ; R15.1@-12.176,25.315 cw(c-12.566,24.924) -12.014,24.924 cw(c-11.462,24.924) R15.1@-11.853,25.315 ; v1@-12.014,24.562 R15.1@-12.014,25.476 ; -12.014,24.848 ccw(c-11.728,24.848) v1@-11.93,24.646 ; v1(-11.811,30.607) -11.811,30.658 -11.633,30.836 -3.333,30.836 -2.25,31.918 U4.2@-2.25,34 ; v1@-11.802,30.598 cw(c-11.228,30.024) -11.228,30.836 ; v1@-11.676,30.472 cw(c-10.799,29.595) -10.799,30.836 ; U5_1.1@36.967,18.35 ccw(c35.775,19.543) 37.461,19.543 ccw(c39.148,19.543) U5_1.1@37.955,18.35 ; U5_1.1@37.093,18.224 ccw(c36.204,19.113) 37.461,19.113 ccw(c38.718,19.113) U5_1.1@37.83,18.224 ; U5_1.1@37.219,18.099 ccw(c36.634,18.684) 37.461,18.684 ccw(c38.289,18.684) U5_1.1@37.704,18.099 ; v1@37.327,22.929 cw(c37.001,22.604) 37.461,22.604 cw(c37.921,22.604) v1@37.596,22.929 ; U5_1.1@37.461,17.628 v1(37.461,23.064) ; v1@38.8,24.646 ccw(c38.352,25.094) 38.986,25.094 ; R15_1.1@38.824,25.315 cw(c38.434,24.924) 38.986,24.924 cw(c39.538,24.924) R15_1.1@39.147,25.315 ; v1@38.986,24.562 R15_1.1@38.986,25.476 ; 38.986,24.848 ccw(c39.272,24.848) v1@39.07,24.646 ; v1(39.189,30.607) 39.189,30.658 39.367,30.836 47.667,30.836 48.75,31.918 U4_1.2@48.75,34 ; v1@39.198,30.598 cw(c39.772,30.024) 39.772,30.836 ; v1@39.324,30.472 cw(c40.201,29.595) 40.201,30.836
  Bottom Layer w0.178: v1@-13.589,22.987 v1(-12.065,24.511) -12.065,30.353 v1(-11.811,30.607) ; v1@-13.539,23.254 ccw(c-13.539,23.777) -13.169,23.407 ; v1@-13.348,23.064 cw(c-12.951,23.064) -13.232,23.344 ; v1@-12.256,24.511 cw(c-12.715,24.511) -12.39,24.186 cw(c-12.065,23.861) v1@-12.065,24.32 ; v1@-12.2,24.646 ccw(c-12.525,24.971) -12.065,24.971 ccw(c-11.605,24.971) v1@-11.93,24.646 ; -12.065,29.534 cw(c-10.738,29.534) v1@-11.676,30.472 ; -12.065,29.963 cw(c-11.167,29.963) v1@-11.802,30.598 ; -12.065,30.392 cw(c-11.596,30.392) v1@-11.928,30.724 ; v1@37.411,22.987 v1(38.935,24.511) 38.935,30.353 v1(39.189,30.607) ; v1@37.461,23.254 ccw(c37.461,23.777) 37.831,23.407 ; v1@37.652,23.064 cw(c38.049,23.064) 37.768,23.344 ; v1@38.744,24.511 cw(c38.285,24.511) 38.61,24.186 cw(c38.935,23.861) v1@38.935,24.32 ; v1@38.8,24.646 ccw(c38.475,24.971) 38.935,24.971 ccw(c39.395,24.971) v1@39.07,24.646 ; 38.935,29.534 cw(c40.262,29.534) v1@39.324,30.472 ; 38.935,29.963 cw(c39.833,29.963) v1@39.198,30.598 ; 38.935,30.392 cw(c39.404,30.392) v1@39.072,30.724
pads on no net: Designator3.0 Designator4.0 Designator5.0 HOLE1.0 HOLE1_1.0 HOLE2.0 HOLE2_1.0 HOLE3.0 HOLE3_1.0 HOLE4.0 HOLE4_1.0 P3.1 P3.2 P3.3 P3.4 P3.5 P3.6 P3.7 P3.8 P3_1.1 P3_1.2 P3_1.3 P3_1.4 P3_1.5 P3_1.6 P3_1.7 P3_1.8 P4.2 P4.3 P4.4 P4.5 P4.6 P4.7 P4.8 P4_1.2 P4_1.3 P4_1.4 P4_1.5 P4_1.6 P4_1.7 P4_1.8 U3.1 U3.8 U3.9 U3_1.1 U3_1.8 U3_1.9 U4.7 U4.12 U4.13 U4.18 U4.24 U4.26 U4.46 U4.47 U4_1.7 U4_1.12 U4_1.13 U4_1.18 U4_1.24 U4_1.26 U4_1.46 U4_1.47 U5.7 U5.8 U5.14 U5_1.7 U5_1.8 U5_1.14 USB1.4 USB1_1.4
copper on no net:
  other v2: 5.033,5.015 13.033,5.015 56.033,5.015 64.033,5.015

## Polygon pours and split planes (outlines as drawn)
GND on Top Layer "Keep-Out Layer-No Net" (solid, remove dead copper, pour order 1000): 76.146,80.137 76.146,-0.127 25.854,-0.127 25.854,80.137
GND on Top Layer "Keep-Out Layer-No Net" (solid, remove dead copper, pour order 1000): 25.146,80.137 25.146,-0.127 -25.146,-0.127 -25.146,80.137
GND on Bottom Layer "Keep-Out Layer-No Net" (solid, remove dead copper, pour order 1001): 76.146,80.137 76.146,-0.127 25.854,-0.127 25.854,80.137
GND on Bottom Layer "Keep-Out Layer-No Net" (solid, remove dead copper, pour order 1001): 25.146,80.137 25.146,-0.127 -25.146,-0.127 -25.146,80.137

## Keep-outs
Keep-Out Layer:
  lines w0.254: -25,23.857 -24.003,22.86 -25,21.863 -25,1 -24,0 24,0 25,1 25,21.844 25,21.863 24.003,22.86 25,23.857 ; -25,23.859 -25,74.984 -23.984,76 -6.028,76 -2.025,80.003 24,80.003 25,79.003 25,23.86 ; 26,23.857 26.997,22.86 26,21.863 26,1 27,0 75,0 76,1 76,21.844 76,21.863 75.003,22.86 76,23.857 ; 26,23.859 26,74.984 27.016,76 44.972,76 48.975,80.003 75,80.003 76,79.003 76,23.86 ; -25,-5 77,-5 77,0 -25,0 -25,-5 ; -25,80.003 77,80.003 77,85.003 -25,85.003 -25,80.003

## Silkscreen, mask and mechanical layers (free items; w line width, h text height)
Top Overlay:
  text "eBox spark v1.2" at -9.144,82.931 h2.54
  text "工艺边" at -22.225,81.407 h3.81
  text "工艺边" at 60.325,81.28 h3.81
  text "90*101mm" at -9.144,80.772 h2.54
  text "D5V" at 18.267,73.098 h1.78
  text "D5V" at 69.267,73.098 h1.78
  text "G" at 6.985,71.374 h1.78 r90
  text "G" at 57.985,71.374 h1.78 r90
  text "IO" at 1.905,71.022 h1.78 r90
  text "IO" at 52.905,71.022 h1.78 r90
  text "GND" at 17.859,70.558 h1.78
  text "GND" at 68.859,70.558 h1.78
  text "TX" at -0.655,70.496 h1.78 r90
  text "TX" at 50.345,70.496 h1.78 r90
  text "RX" at -3.195,70.406 h1.78 r90
  text "RX" at 47.805,70.406 h1.78 r90
  text "~" at 18.034,69.596 h3.05 r180
  text "~" at 69.034,69.596 h3.05 r180
  text "D5V" at -5.715,69.523 h1.78 r90
  text "D5V" at 45.285,69.523 h1.78 r90
  text "CLK" at 4.445,69.469 h1.78 r90
  text "CLK" at 55.445,69.469 h1.78 r90
  text "3V3" at -21.269,68.072 h1.78
  text "3V3" at 29.731,68.072 h1.78
  text "PB0" at 18.417,68.017 h1.78
  text "PB0" at 69.417,68.017 h1.78
  text "~" at 18.034,66.929 h3.05 r180
  text "~" at 69.034,66.929 h3.05 r180
  text "GND" at -21.269,65.659 h1.78
  text "GND" at 29.731,65.659 h1.78
  text "PB1" at 18.417,65.457 h1.78
  text "PB1" at 69.417,65.457 h1.78
  text "~" at -16.891,64.77 h3.05 r180
  text "~" at 34.109,64.77 h3.05 r180
  text "PA0" at -21.269,63.119 h1.78
  text "PA0" at 29.731,63.119 h1.78
  text "PB2" at 18.417,62.917 h1.78
  text "PB2" at 69.417,62.917 h1.78
  text "~" at -16.891,61.976 h3.05 r180
  text "~" at 34.109,61.976 h3.05 r180
  text "PA1" at -21.269,60.554 h1.78
  text "PA1" at 29.731,60.554 h1.78
  text "PB3" at 18.413,60.396 h1.78
  text "PB3" at 69.413,60.396 h1.78
  text "~" at -16.891,59.563 h3.05 r180
  text "~" at 34.109,59.563 h3.05 r180
  text "PA2" at -21.269,58.005 h1.78
  text "PA2" at 29.731,58.005 h1.78
  text "PB4" at 18.418,57.836 h1.78
  text "PB4" at 69.418,57.836 h1.78
  text "~" at -16.891,57.023 h3.05 r180
  text "~" at 34.109,57.023 h3.05 r180
  text "PA3" at -21.269,55.474 h1.78
  text "PA3" at 29.731,55.474 h1.78
  text "PB5" at 18.405,55.316 h1.78
  text "PB5" at 69.405,55.316 h1.78
  text "~" at -16.891,54.483 h3.05 r180
  text "~" at 34.109,54.483 h3.05 r180
  text "PA4" at -21.269,52.908 h1.78
  text "PA4" at 29.731,52.908 h1.78
  text "PB6" at 18.413,52.776 h1.78
  text "PB6" at 69.413,52.776 h1.78
  text "~" at -16.891,51.943 h3.05 r180
  text "~" at 34.109,51.943 h3.05 r180
  text "PA5" at -21.269,50.377 h1.78
  text "PA5" at 29.731,50.377 h1.78
  text "PB7" at 18.413,50.216 h1.78
  text "PB7" at 69.413,50.216 h1.78
  text "RST" at 11.049,50.038 h1.78
  text "RST" at 62.049,50.038 h1.78
  text "KEY" at -14.351,50.017 h1.78
  text "KEY" at 36.649,50.017 h1.78
  text "~" at -16.891,49.276 h3.05 r180
  text "~" at 34.109,49.276 h3.05 r180
  text "PA6" at -21.269,47.828 h1.78
  text "PA6" at 29.731,47.828 h1.78
  text "PB8" at 18.412,47.695 h1.78
  text "PB8" at 69.412,47.695 h1.78
  text "~" at -16.891,46.736 h3.05 r180
  text "~" at 34.109,46.736 h3.05 r180
  text "PA7" at -21.269,45.263 h1.78
  text "PA7" at 29.731,45.263 h1.78
  text "PB9" at 18.412,45.155 h1.78
  text "PB9" at 69.412,45.155 h1.78
  text "LED1" at 9.525,43.815 h1.78
  text "LED1" at 60.525,43.815 h1.78
  text "PA8" at -21.269,42.731 h1.78
  text "PA8" at 29.731,42.731 h1.78
  text "PB10" at 17.531,42.614 h1.78
  text "PB10" at 68.531,42.614 h1.78
  text "LED2" at 9.525,42.545 h1.78
  text "LED2" at 60.525,42.545 h1.78
  text "PA9" at -21.269,40.183 h1.78
  text "PA9" at 29.731,40.183 h1.78
  text "PB11" at 17.748,40.054 h1.78
  text "PB11" at 68.748,40.054 h1.78
  text "PA10" at -21.269,37.634 h1.78
  text "PA10" at 29.731,37.634 h1.78
  text "PB12" at 17.539,37.514 h1.78
  text "PB12" at 68.539,37.514 h1.78
  text "PA11" at -21.269,35.069 h1.78
  text "PA11" at 29.731,35.069 h1.78
  text "PB13" at 17.528,34.994 h1.78
  text "PB13" at 68.528,34.994 h1.78
  text "PA12" at -21.269,32.52 h1.78
  text "PA12" at 29.731,32.52 h1.78
  text "PB14" at 17.533,32.434 h1.78
  text "PB14" at 68.533,32.434 h1.78
  text "PA13" at -21.269,29.989 h1.78
  text "PA13" at 29.731,29.989 h1.78
  text "PB15" at 17.52,29.913 h1.78
  text "PB15" at 68.52,29.913 h1.78
  text "PA14" at -21.269,27.424 h1.78
  text "PA14" at 29.731,27.424 h1.78
  text "D3V3" at 17.441,27.373 h1.78
  text "D3V3" at 68.441,27.373 h1.78
  text "PA15" at -21.269,24.892 h1.78
  text "PA15" at 29.731,24.892 h1.78
  text "GND" at 17.859,24.833 h1.78
  text "GND" at 68.859,24.833 h1.78
  text "A" at 5.08,24.384 h15
  text "A" at 56.08,24.384 h15
  text "NC" at -20.997,19.712 h1.78
  text "NC" at 30.003,19.712 h1.78
  text "RST" at 18.181,19.685 h1.78
  text "RST" at 69.181,19.685 h1.78
  text "NC" at 19.113,17.212 h1.78
  text "NC" at 70.113,17.212 h1.78
  text "NC" at -20.997,17.172 h1.78
  text "NC" at 30.003,17.172 h1.78
  text "NC" at 19.113,14.672 h1.78
  text "NC" at 70.113,14.672 h1.78
  text "NC" at -20.997,14.632 h1.78
  text "NC" at 30.003,14.632 h1.78
  text "NC" at 19.113,12.131 h1.78
  text "NC" at 70.113,12.131 h1.78
  text "NC" at -20.997,12.091 h1.78
  text "NC" at 30.003,12.091 h1.78
  text "eBox-SPARK_1.2" at 3.175,11.43 h1.78
  text "eBox-SPARK_1.2" at 54.175,11.43 h1.78
  text "2018/12/25" at 3.048,9.652 h1.78
  text "2018/12/25" at 54.048,9.652 h1.78
  text "NC" at 19.113,9.591 h1.78
  text "NC" at 70.113,9.591 h1.78
  text "NC" at -20.997,9.551 h1.78
  text "NC" at 30.003,9.551 h1.78
  text "NC" at 19.113,7.051 h1.78
  text "NC" at 70.113,7.051 h1.78
  text "NC" at -20.997,7.011 h1.78
  text "NC" at 30.003,7.011 h1.78
  text "NC" at 19.113,4.511 h1.78
  text "NC" at 70.113,4.511 h1.78
  text "NC" at 19.113,1.971 h1.78
  text "NC" at 70.113,1.971 h1.78
  text "工艺边" at -22.225,-3.683 h3.81
  text "工艺边" at 60.325,-3.81 h3.81
Bottom Overlay:
  lines w0.203: -24.13,29.21 -13.081,29.21 ; -24.13,34.29 -13.081,34.29 ; -24.13,44.45 -13.081,44.45 ; -24.13,54.61 -13.081,54.61 ; -18.669,44.45 -18.669,62.23 -13.081,62.23 ; -15.494,29.21 -15.494,31.75 -18.669,31.75 -18.669,34.29 -18.669,41.91 -13.081,41.91 ; 10.16,29.21 24.13,29.21 ; 10.16,36.83 24.13,36.83 ; 10.16,39.37 24.13,39.37 ; 10.16,44.45 24.13,44.45 ; 10.16,49.53 19.177,49.53 ; 10.16,54.102 19.177,54.102 19.177,44.45 ; 10.16,57.15 24.13,57.15 ; 10.16,64.77 24.13,64.77 ; 13.97,44.45 13.97,41.91 18.034,41.91 18.034,39.37 ; 26.87,29.21 37.919,29.21 ; 26.87,34.29 37.919,34.29 ; 26.87,44.45 37.919,44.45 ; 26.87,54.61 37.919,54.61 ; 32.331,44.45 32.331,62.23 37.919,62.23 ; 35.506,29.21 35.506,31.75 32.331,31.75 32.331,34.29 32.331,41.91 37.919,41.91 ; 61.16,29.21 75.13,29.21 ; 61.16,36.83 75.13,36.83 ; 61.16,39.37 75.13,39.37 ; 61.16,44.45 75.13,44.45 ; 61.16,49.53 70.177,49.53 ; 61.16,54.102 70.177,54.102 70.177,44.45 ; 61.16,57.15 75.13,57.15 ; 61.16,64.77 75.13,64.77 ; 64.97,44.45 64.97,41.91 69.034,41.91 69.034,39.37 ; -24.13,24.13 -13.081,24.13 -13.081,64.77 -24.13,64.77 -24.13,24.13 ; 10.16,24.13 10.16,69.85 24.13,69.85 24.13,24.13 10.16,24.13 ; 26.87,24.13 37.919,24.13 37.919,64.77 26.87,64.77 26.87,24.13 ; 61.16,24.13 61.16,69.85 75.13,69.85 75.13,24.13 61.16,24.13
  text "TIM3" at 17.653,68.326 h1.78
  text "TIM3" at 68.653,68.326 h1.78
  text "C3" at 21.506,68.199 h1.78
  text "C3" at 72.506,68.199 h1.78
  text "C4" at 21.506,65.659 h1.78
  text "C4" at 72.506,65.659 h1.78
  text "TIM2" at -13.716,63.119 h1.78
  text "TIM2" at 37.284,63.119 h1.78
  text "C1" at -19.889,62.992 h1.78
  text "C1" at 31.111,62.992 h1.78
  text "C2" at -19.68,60.452 h1.78
  text "C2" at 31.32,60.452 h1.78
  text "UART2" at -13.736,60.198 h1.78 r90
  text "UART2" at 37.264,60.198 h1.78 r90
  text "C3" at -19.668,57.912 h1.78
  text "C3" at 31.332,57.912 h1.78
  text "T" at -16.764,57.785 h1.78
  text "T" at 34.236,57.785 h1.78
  text "C4" at -19.673,55.372 h1.78
  text "R" at -16.764,55.372 h1.78
  text "C4" at 31.327,55.372 h1.78
  text "R" at 34.236,55.372 h1.78
  text "TIM4" at 21.463,55.245 h1.78
  text "TIM4" at 72.463,55.245 h1.78
  text "I2C1" at 12.233,53.721 h1.78 r90
  text "I2C1" at 63.233,53.721 h1.78 r90
  text "C1" at 21.506,52.832 h1.78
  text "C1" at 72.506,52.832 h1.78
  text "SCL" at 17.653,52.705 h1.78
  text "SCL" at 68.653,52.705 h1.78
  text "SPI1" at -14.224,52.324 h1.78
  text "SPI1" at 36.776,52.324 h1.78
  text "TIM3" at -18.669,51.689 h1.78
  text "TIM3" at 32.331,51.689 h1.78
  text "C2" at 21.506,50.292 h1.78
  text "C2" at 72.506,50.292 h1.78
  text "SCK" at -14.605,50.165 h1.78
  text "SDA" at 17.653,50.165 h1.78
  text "SCK" at 36.395,50.165 h1.78
  text "SDA" at 68.653,50.165 h1.78
  text "CAN" at 12.233,48.895 h1.78 r90
  text "CAN" at 63.233,48.895 h1.78 r90
  text "C1" at -19.889,47.752 h1.78
  text "R" at 17.653,47.752 h1.78
  text "C3" at 21.506,47.752 h1.78
  text "C1" at 31.111,47.752 h1.78
  text "R" at 68.653,47.752 h1.78
  text "C3" at 72.506,47.752 h1.78
  text "MISO" at -13.97,47.625 h1.78
  text "MISO" at 37.03,47.625 h1.78
  text "C2" at -19.68,45.212 h1.78
  text "MOSI" at -13.97,45.212 h1.78
  text "T" at 17.653,45.212 h1.78
  text "C4" at 21.506,45.212 h1.78
  text "C2" at 31.32,45.212 h1.78
  text "MOSI" at 37.03,45.212 h1.78
  text "T" at 68.653,45.212 h1.78
  text "C4" at 72.506,45.212 h1.78
  text "TIM1" at -13.716,42.799 h1.78
  text "TIM1" at 37.284,42.799 h1.78
  text "C1" at -19.889,42.672 h1.78
  text "I2C2" at 17.653,42.672 h1.78
  text "SCL" at 21.506,42.672 h1.78
  text "C1" at 31.111,42.672 h1.78
  text "I2C2" at 68.653,42.672 h1.78
  text "SCL" at 72.506,42.672 h1.78
  text "T" at 11.976,42.545 h1.78
  text "T" at 62.976,42.545 h1.78
  text "Keil MDK-ARM" at -1.374,41.402 h2.54 r270
  text "eBox" at 1.42,41.402 h2.54 r270
  text "eBox-SPARK" at 4.341,41.402 h2.54 r270
  text "Keil MDK-ARM" at 49.626,41.402 h2.54 r270
  text "eBox" at 52.42,41.402 h2.54 r270
  text "eBox-SPARK" at 55.341,41.402 h2.54 r270
  text "UART1" at -13.736,41.021 h1.78 r90
  text "UART1" at 37.264,41.021 h1.78 r90
  text "C2" at -19.68,40.132 h1.78
  text "SDA" at 21.506,40.132 h1.78
  text "C2" at 31.32,40.132 h1.78
  text "SDA" at 72.506,40.132 h1.78
  text "R" at 12.075,40.005 h1.78
  text "UART3" at 17.653,40.005 h1.78
  text "R" at 63.075,40.005 h1.78
  text "UART3" at 68.653,40.005 h1.78
  text "T" at -16.891,39.878 h1.78
  text "T" at 34.109,39.878 h1.78
  text "C3" at -19.668,37.592 h1.78
  text "R" at -16.891,37.592 h1.78
  text "C3" at 31.332,37.592 h1.78
  text "R" at 34.109,37.592 h1.78
  text "TFCARD_CS" at 21.463,37.465 h1.78
  text "TFCARD_CS" at 72.463,37.465 h1.78
  text "C4" at -19.673,35.179 h1.78
  text "C4" at 31.327,35.179 h1.78
  text "SCK" at 21.506,35.052 h1.78
  text "SCK" at 72.506,35.052 h1.78
  text "SPI2" at 12.233,34.29 h1.78 r90
  text "SPI2" at 63.233,34.29 h1.78 r90
  text "DM" at -19.321,32.639 h1.78
  text "CAN" at -15.24,32.639 h1.78
  text "R" at -13.716,32.639 h1.78
  text "DM" at 31.679,32.639 h1.78
  text "CAN" at 35.76,32.639 h1.78
  text "R" at 37.284,32.639 h1.78
  text "MISO" at 21.506,32.512 h1.78
  text "MISO" at 72.506,32.512 h1.78
  text "DP" at -19.533,29.972 h1.78
  text "T" at -13.716,29.972 h1.78
  text "MOSI" at 21.506,29.972 h1.78
  text "DP" at 31.467,29.972 h1.78
  text "T" at 37.284,29.972 h1.78
  text "MOSI" at 72.506,29.972 h1.78
  text "USB" at -16.002,29.845 h1.78
  text "USB" at 34.998,29.845 h1.78
  text "SWD" at -13.736,28.321 h1.78 r90
  text "SWD" at 37.264,28.321 h1.78 r90
  text "Copyright 2016 shentq.All right reserved" at -9.375,27.94 h1.78 r270
  text "-----------------------------------------------------------" at -7.874,27.94 h1.78 r270
  text "www.antsmaker.cn" at -6.835,27.94 h2.54 r270
  text "-----------------------------------------------------------" at -5.08,27.94 h1.78 r270
  text "MADE IN CHINA" at -4.168,27.94 h2.54 r270
  text "-----------------------------------------------------------" at -2.286,27.94 h1.78 r270
  text "PLATFORM" at -1.38,27.94 h1.78 r270
  text "-----------------------------------------------------------" at 0.508,27.94 h1.78 r270
  text "SOFTWARE" at 1.41,27.94 h1.78 r270
  text "-----------------------------------------------------------" at 3.302,27.94 h1.78 r270
  text "BOARD MODEL" at 4.335,27.94 h1.78 r270
  text "___________________________________" at 6.754,27.94 h1.78 r270
  text "Copyright 2016 shentq.All right reserved" at 41.625,27.94 h1.78 r270
  text "-----------------------------------------------------------" at 43.126,27.94 h1.78 r270
  text "www.antsmaker.cn" at 44.165,27.94 h2.54 r270
  text "-----------------------------------------------------------" at 45.92,27.94 h1.78 r270
  text "MADE IN CHINA" at 46.832,27.94 h2.54 r270
  text "-----------------------------------------------------------" at 48.714,27.94 h1.78 r270
  text "PLATFORM" at 49.62,27.94 h1.78 r270
  text "-----------------------------------------------------------" at 51.508,27.94 h1.78 r270
  text "SOFTWARE" at 52.41,27.94 h1.78 r270
  text "-----------------------------------------------------------" at 54.302,27.94 h1.78 r270
  text "BOARD MODEL" at 55.335,27.94 h1.78 r270
  text "___________________________________" at 57.754,27.94 h1.78 r270
  text "___________________________________" at -10.01,27.686 h1.78 r270
  text "___________________________________" at 40.99,27.686 h1.78 r270
  text "IO" at -20.09,27.432 h1.78
  text "D3V3" at 21.463,27.432 h1.78
  text "IO" at 30.91,27.432 h1.78
  text "D3V3" at 72.463,27.432 h1.78
  text "CLK" at -18.538,24.892 h1.78
  text "GND" at 21.463,24.892 h1.78
  text "CLK" at 32.462,24.892 h1.78
  text "GND" at 72.463,24.892 h1.78
  text "eBox" at 6.754,24.257 h5.08
  text "eBox" at 57.754,24.257 h5.08
Top Solder:
  lines w0.508: -24.638,1.143 -24.638,21.717 -23.495,22.86 -23.622,22.987 -24.638,24.003 -24.638,74.803 -23.749,75.692 -6.096,75.692 -5.842,75.692 -1.905,79.629 20.193,79.629 24.003,79.629 24.638,78.994 24.638,78.74 24.638,24.003 23.495,22.86 23.622,22.733 24.638,21.717 24.638,1.143 24.638,1.016 24.003,0.381 -23.876,0.381 -24.638,1.143 ; 26.362,1.143 26.362,21.717 27.505,22.86 27.378,22.987 26.362,24.003 26.362,74.803 27.251,75.692 44.904,75.692 45.158,75.692 49.095,79.629 71.193,79.629 75.003,79.629 75.638,78.994 75.638,78.74 75.638,24.003 74.495,22.86 74.622,22.733 75.638,21.717 75.638,1.143 75.638,1.016 75.003,0.381 27.124,0.381 26.362,1.143
  text "eBox-SPARK" at -1.905,76.454 h3.81
  text "eBox-SPARK" at 49.095,76.454 h3.81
